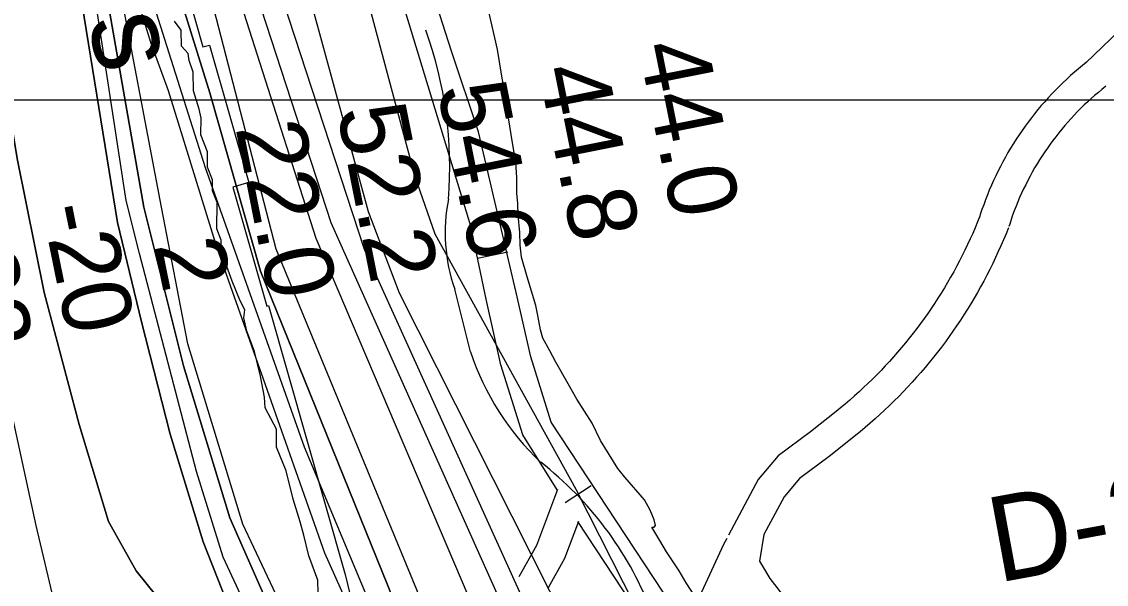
# Model space of a CAD drawing. Extents: x 3250478 to 3288318, y 788638 to 816472.
# Drawn here: x 3277334 to 3278390, y 799603 to 800152 of the extents above; entities that cross this region are included whole.
import ezdxf

# ---------------------------------------------------------------- set-up
doc = ezdxf.new("R2010")
doc.units = 0
for name, color, linetype in [('V-GRID-MAJR', 7, 'Continuous'), ('V-RIVR-EDGE', 7, 'Continuous'), ('V-RIVR-IDEN', 7, 'Continuous'), ('V-RIVR-RANG', 7, 'Continuous'), ('V-RIVR-RANG-IDEN', 7, 'Continuous'), ('V-ROAD-CNTR', 7, 'Continuous'), ('V-RRAP-RVMT', 7, 'Continuous'), ('V-SITE-VEGE', 7, 'Continuous'), ('V-TOPO-DPTH', 7, 'Continuous'), ('V-TOPO-MAJR', 7, 'Continuous'), ('V-TOPO-MINR', 7, 'Continuous'), ('V-TOPO-WATR', 7, 'Continuous')]:
    doc.layers.add(name, color=color, linetype=linetype)

msp = doc.modelspace()

# ---------------------------------------------------------------- linework, layer by layer
at = {"layer": 'V-GRID-MAJR'}
msp.add_spline([(3254640.8, 800084.8), (3259879.3, 800081.4), (3265117.8, 800078.7), (3270356.3, 800076.8), (3275594.8, 800075.6), (3280833.3, 800075.3), (3286071.8, 800075.6)], degree=3, dxfattribs=at)
at = {"layer": 'V-RIVR-EDGE'}
msp.add_lwpolyline([(3277622.9, 799594.3), (3277622.5, 799607.3), (3277613.9, 799631.3), (3277609.1, 799651.3), (3277605.3, 799664.3), (3277598.4, 799686.5), (3277591.9, 799713.9), (3277582.4, 799737), (3277582.4, 799754.4), (3277571.2, 799775.3), (3277570.8, 799785.7), (3277566.9, 799806.1), (3277560.9, 799830.1), (3277553.6, 799850.1), (3277550.5, 799863.1), (3277551.4, 799870.9), (3277547.1, 799879.6), (3277539.3, 799898.8), (3277528.5, 799928.4), (3277528.6, 799938.8), (3277524.2, 799949.7), (3277524.7, 799975.3), (3277520, 799986.6), (3277520, 799997.5), (3277515.3, 800009.7), (3277515.3, 800024.9), (3277508.8, 800041.4), (3277508.9, 800057.5), (3277507.1, 800066.2), (3277501.5, 800084.1), (3277501.2, 800102.3), (3277497.3, 800113.6), (3277496.4, 800120.6), (3277489.9, 800127.6), (3277489.5, 800143.2), (3277483, 800151.9)], dxfattribs=at)
at = {"layer": 'V-ROAD-CNTR'}
for p, q in [((3277778, 799921.2), (3277807.4, 799927.3)), ((3277863.3, 799683.2), (3277888.4, 799699.7))]:
    msp.add_line(p, q, dxfattribs=at)
for points in [[(3279206.2, 801012.6), (3278974.9, 800774.4), (3278783.1, 800571.1), (3278696.4, 800456.4), (3278675.3, 800415.4), (3278649.7, 800380.5), (3278586.3, 800330.4), (3278557.4, 800304.9), (3278515.8, 800254.1), (3278461.1, 800199.6), (3278369.5, 800111.1)], [(3277855.6, 799695.3), (3277822.2, 799748.9), (3277800.7, 799817.2), (3277786.4, 799881.3), (3277771.5, 799952.3), (3277687.1, 800229.7), (3277671.3, 800298.1), (3277660.2, 800373), (3277640.5, 800571.9), (3277629.6, 800720), (3277620.5, 800771.6), (3277617.5, 800779.9), (3277610.4, 800799.8), (3277603, 800812.8), (3277587.2, 800838.8), (3277571.1, 800862.2), (3277549.7, 800897.4)], [(3278293.9, 798738.3), (3278286.8, 798822.7), (3278277.1, 798881.5), (3278266.1, 798928.8), (3278223.6, 799045.9), (3278211.5, 799073.6), (3278202.3, 799097.7), (3278195.5, 799120.9), (3278187.8, 799144.6), (3278182.8, 799165.7), (3278177.1, 799193.2), (3278157.9, 799287), (3278147.5, 799319.4), (3278013, 799513), (3277849.7, 799761.5), (3277829.7, 799825), (3277815.7, 799887.6), (3277778.8, 800044.2), (3277752.5, 800122.8), (3277716.1, 800237.6)], [(3278370.6, 800112), (3278366.7, 800108.9), (3278362.8, 800105.7), (3278358.9, 800102.3), (3278355, 800099), (3278351.3, 800095.5), (3278347.6, 800092), (3278343.9, 800088.5), (3278340.3, 800084.8), (3278336.8, 800081.2), (3278333.3, 800077.4), (3278329.9, 800073.6), (3278326.6, 800069.8), (3278323.3, 800065.9), (3278320.1, 800061.9), (3278316.9, 800057.9), (3278313.8, 800053.8), (3278310.8, 800049.7), (3278307.9, 800045.5), (3278305, 800041.3), (3278302.2, 800037.1), (3278299.4, 800032.8), (3278296.7, 800028.4), (3278294.1, 800024), (3278291.6, 800019.6), (3278289.2, 800015.1), (3278286.8, 800010.6), (3278284.5, 800006.1), (3278282.3, 800001.5), (3278280.1, 799996.8), (3278278, 799992.2), (3278276, 799987.5), (3278274.1, 799982.8), (3278272.3, 799978), (3278270.5, 799973.2), (3278268.8, 799968.4), (3278267.2, 799963.6), (3278266.4, 799960.9)], [(3278389.3, 800088.6), (3278385.6, 800085.6), (3278382.1, 800082.7), (3278378.5, 800079.7), (3278375.1, 800076.6), (3278371.7, 800073.5), (3278368.3, 800070.4), (3278365, 800067.2), (3278361.8, 800063.9), (3278358.6, 800060.6), (3278355.5, 800057.2), (3278352.4, 800053.8), (3278349.4, 800050.3), (3278346.4, 800046.7), (3278343.5, 800043.2), (3278340.6, 800039.5), (3278337.9, 800035.9), (3278335.1, 800032.2), (3278332.5, 800028.4), (3278329.9, 800024.6), (3278327.3, 800020.8), (3278324.9, 800016.9), (3278322.4, 800012.9), (3278320.1, 800009), (3278317.8, 800005), (3278315.6, 800000.9), (3278313.5, 799996.8), (3278311.4, 799992.7), (3278309.4, 799988.6), (3278307.4, 799984.4), (3278305.5, 799980.2), (3278303.7, 799976), (3278302, 799971.7), (3278300.3, 799967.4), (3278298.7, 799963.1), (3278297.2, 799958.7), (3278295.8, 799954.3), (3278295, 799951.9)], [(3278266.8, 799962), (3278264.5, 799956.4), (3278262.2, 799950.8), (3278259.8, 799945.3), (3278257.4, 799939.9), (3278254.9, 799934.5), (3278252.3, 799929.1), (3278249.6, 799923.7), (3278246.9, 799918.4), (3278244.1, 799913.1), (3278241.3, 799907.8), (3278238.3, 799902.6), (3278235.3, 799897.4), (3278232.3, 799892.3), (3278229.2, 799887.2), (3278226, 799882.2), (3278222.7, 799877.1), (3278219.4, 799872.2), (3278216, 799867.2), (3278212.6, 799862.4), (3278209, 799857.5), (3278205.5, 799852.7), (3278201.8, 799848), (3278198.1, 799843.3), (3278194.4, 799838.6), (3278190.5, 799834), (3278186.7, 799829.5), (3278182.7, 799825), (3278178.7, 799820.5), (3278174.7, 799816.1), (3278170.6, 799811.8), (3278166.4, 799807.5), (3278162.2, 799803.3), (3278157.9, 799799.1), (3278153.6, 799795), (3278149.2, 799790.9), (3278144.8, 799786.9), (3278140.3, 799782.9), (3278135.7, 799779), (3278131.1, 799775.2), (3278128.5, 799773)], [(3278294.6, 799950.8), (3278292.3, 799945), (3278289.8, 799939.1), (3278287.3, 799933.3), (3278284.7, 799927.5), (3278282, 799921.7), (3278279.3, 799915.9), (3278276.4, 799910.2), (3278273.5, 799904.6), (3278270.6, 799898.9), (3278267.5, 799893.3), (3278264.4, 799887.8), (3278261.2, 799882.3), (3278258, 799876.8), (3278254.6, 799871.4), (3278251.2, 799866), (3278247.8, 799860.6), (3278244.2, 799855.3), (3278240.6, 799850.1), (3278236.9, 799844.9), (3278233.2, 799839.7), (3278229.4, 799834.6), (3278225.5, 799829.6), (3278221.6, 799824.6), (3278217.6, 799819.6), (3278213.5, 799814.7), (3278209.4, 799809.9), (3278205.2, 799805.1), (3278200.9, 799800.3), (3278196.6, 799795.7), (3278192.2, 799791), (3278187.8, 799786.5), (3278183.3, 799782), (3278178.7, 799777.5), (3278174.1, 799773.1), (3278169.5, 799768.8), (3278164.8, 799764.5), (3278160, 799760.3), (3278155.1, 799756.1), (3278150.3, 799752.1), (3278147.5, 799749.8)], [(3277771.1, 799830), (3277755.8, 799891)], [(3278128.6, 799773.1), (3278102, 799751.8), (3278070.6, 799728.5), (3278051.2, 799705.5), (3278022.3, 799651.3)], [(3278147.3, 799749.7), (3278120.3, 799728), (3278091.3, 799706.5), (3278076.2, 799688.6), (3278056.6, 799651.9)], [(3277855.9, 799695.8), (3277835.3, 799641.1), (3277818.3, 799610.7)], [(3277876.2, 799664.6), (3277862.5, 799628.5), (3277846.6, 799600)], [(3278271.3, 798417), (3278259.6, 798458.4), (3278253, 798493.7), (3278253, 798516.9), (3278254.7, 798547.2), (3278260.8, 798616.3), (3278264.9, 798670.5), (3278263.9, 798736.8), (3278257, 798818.9), (3278247.6, 798875.7), (3278237, 798921.3), (3278226.4, 798958.6), (3278158.9, 799136.5), (3278153.5, 799159.2), (3278147.7, 799187.2), (3278128.9, 799279.3), (3277937, 799571.3), (3277875.6, 799664.6)], [(3278056.6, 799651.9), (3278052.5, 799626), (3278055.3, 799621.2)], [(3278020.6, 799648.2), (3278017.4, 799642.2), (3277976.4, 799553.6)], [(3278055.3, 799621.2), (3278062.3, 799609.1), (3278108.5, 799549.8), (3278132.3, 799509.1), (3278142.7, 799477.8)]]:
    msp.add_lwpolyline(points, dxfattribs=at)
for centre, radius, start, end in [((3277353.6, 800009.4), 397.3, 355.5654, 19.6998), ((3277913.3, 799946.1), 166.9, 168.7185, 199.2768), ((3278019.3, 799912), 261.4, 198.2915, 226.5653), ((3277630.5, 799454.8), 339.5, 21.6518, 51.9798)]:
    msp.add_arc(centre, radius, start, end, dxfattribs=at)
at = {"layer": 'V-RRAP-RVMT'}
for p, q in [((3277477.9, 800242.4), (3277510.7, 800126.9)), ((3277510.7, 800126.9), (3277517.3, 800128.8)), ((3277517.3, 800128.8), (3277555.4, 799994.8)), ((3277555.4, 799994.8), (3277539.9, 799990.3)), ((3277539.9, 799990.3), (3277573, 799874.4)), ((3277573, 799874.4), (3277574.7, 799874.9)), ((3277574.7, 799874.9), (3277649.1, 799612.9)), ((3277649.1, 799612.9), (3277681.5, 799481.6))]:
    msp.add_line(p, q, dxfattribs=at)
at = {"layer": 'V-SITE-VEGE'}
for p, q in [((3277797.5, 800124.5), (3277788.8, 800162.6)), ((3277801.4, 800100.3), (3277797.5, 800124.5)), ((3277804, 800085.8), (3277801.4, 800100.3)), ((3277806.8, 800065.9), (3277804, 800085.8)), ((3277810.8, 800041.7), (3277806.8, 800065.9)), ((3277813.5, 800023.9), (3277810.8, 800041.7)), ((3277815.4, 800014.3), (3277813.5, 800023.9)), ((3277816.3, 799999.7), (3277815.4, 800014.3)), ((3277816.3, 799984.6), (3277816.3, 799999.7)), ((3277817.1, 799974.3), (3277816.3, 799984.6)), ((3277817.4, 799963), (3277817.1, 799974.3)), ((3277819, 799946.3), (3277817.4, 799963)), ((3277819.4, 799933.9), (3277819, 799946.3)), ((3277820.8, 799922.1), (3277819.4, 799933.9)), ((3277826.3, 799902.8), (3277820.8, 799922.1)), ((3277834.7, 799874.9), (3277826.3, 799902.8)), ((3277836.6, 799865.3), (3277834.7, 799874.9)), ((3277839.2, 799851.3), (3277836.6, 799865.3)), ((3277841.6, 799843.3), (3277839.2, 799851.3)), ((3277848.4, 799831), (3277841.6, 799843.3)), ((3277854.1, 799819.9), (3277848.4, 799831)), ((3277866.1, 799798.6), (3277854.1, 799819.9)), ((3277874.7, 799783.7), (3277866.1, 799798.6)), ((3277889.4, 799760.4), (3277874.7, 799783.7)), ((3277897.5, 799743.4), (3277889.4, 799760.4)), ((3277914.5, 799716.3), (3277897.5, 799743.4)), ((3277921.2, 799707.9), (3277914.5, 799716.3)), ((3277940.3, 799685.8), (3277921.2, 799707.9)), ((3277946, 799675.7), (3277940.3, 799685.8)), ((3277950, 799666.1), (3277946, 799675.7)), ((3277949.7, 799659), (3277951.3, 799660.7)), ((3277951.3, 799660.7), (3277950, 799666.1)), ((3277955.5, 799646.2), (3277947.6, 799659)), ((3277947.6, 799659), (3277949.7, 799659)), ((3277961.8, 799635.1), (3277955.5, 799646.2)), ((3277974.2, 799616.5), (3277961.8, 799635.1)), ((3277981.1, 799604.9), (3277974.2, 799616.5)), ((3277990.7, 799590), (3277981.1, 799604.9))]:
    msp.add_line(p, q, dxfattribs=at)
at = {"layer": 'V-TOPO-DPTH'}
for points in [[(3278043.5, 798542.7), (3277830.5, 799256.4), (3277566.9, 799908.5), (3277517.6, 800082.3), (3277468.3, 800241), (3277429.8, 800571.3), (3277421.2, 800642.1), (3277410.6, 800987.4), (3277400, 801210.5), (3277393.5, 801266.3), (3277350.7, 801538.7), (3277329.3, 801695.2), (3277325.1, 801815.3), (3277325.1, 801924.7), (3277278.1, 802561.8), (3277267.4, 802639), (3277188.2, 803185.9), (3277171.1, 803391.8), (3277162.6, 803604.2), (3277160.5, 803885.2), (3277160.6, 804026.7), (3277152, 804061), (3277098.4, 804232.6), (3276937.7, 804777.5)], [(3276847.8, 804710), (3276986.9, 804194.1), (3277031.9, 804016), (3277102.5, 803454.1), (3277138.9, 803192.4), (3277158.1, 803005.8), (3277207.3, 802486.7), (3277260.7, 801884), (3277305.7, 801504.4), (3277359.2, 801223.4), (3277382.6, 800685), (3277391.2, 800526.3), (3277412.5, 800204.6), (3277453.2, 799970.8), (3277491.8, 799816.3), (3277536.8, 799668.3), (3277575.4, 799580.4), (3277620.4, 799498.8), (3277676.1, 799421.6), (3277755.4, 799312.2), (3277770.4, 799280), (3277813.3, 799119.2), (3277974, 798523.5)], [(3277974, 798523.5), (3277813.3, 799119.2), (3277770.4, 799280), (3277755.4, 799312.2), (3277676.1, 799421.6), (3277620.4, 799498.8), (3277575.4, 799580.4), (3277536.8, 799668.3), (3277491.8, 799816.3), (3277453.2, 799970.8), (3277412.5, 800204.6), (3277391.2, 800526.3), (3277382.6, 800685), (3277359.2, 801223.4), (3277305.7, 801504.4), (3277260.7, 801884), (3277207.3, 802486.7), (3277158.1, 803005.8), (3277138.9, 803192.4), (3277102.5, 803454.1), (3277031.9, 804016), (3276986.9, 804194.1), (3276847.8, 804710)], [(3277384.9, 801221.2), (3277410.5, 800597.1), (3277434, 800236.7), (3277434, 800215.3), (3277459.7, 800131.6), (3277476.8, 800084.4), (3277524, 799932.1), (3277573.3, 799792.7), (3277629, 799634), (3277676.1, 799528.9), (3277721.2, 799421.6), (3277770.5, 799320.8), (3277791.9, 799282.2), (3277839, 799091.3), (3278011, 798533.7)], [(3277384.9, 801221.2), (3277410.5, 800597.1), (3277434, 800236.7), (3277434, 800215.3), (3277459.7, 800131.6), (3277476.8, 800084.4), (3277524, 799932.1), (3277573.3, 799792.7), (3277629, 799634), (3277676.1, 799528.9), (3277721.2, 799421.6), (3277770.5, 799320.8), (3277791.9, 799282.2), (3277839, 799091.3), (3278011, 798533.7)], [(3276789.3, 799207.8), (3276858.5, 799246.1), (3276865.5, 799249.3), (3277370.8, 799382.9), (3277382.2, 799397.5), (3277388.4, 799421.9), (3277391.8, 799446.3), (3277391, 799471), (3277387.4, 799495.9), (3277348.6, 799660.8), (3277325, 799768.5), (3277303.6, 799876.6), (3277285.4, 799985.3), (3277269.4, 800094.4), (3277225.6, 800429.4), (3277223.2, 800450.5), (3277221.2, 800471.7), (3277219.9, 800492.8), (3277219.1, 800514.1), (3277218.7, 800535.3), (3277218.4, 800556.6), (3277218.1, 800577.8), (3277217.9, 800599.1), (3277214.3, 801050.6)], [(3276789.3, 799207.8), (3276858.5, 799246.1), (3276865.5, 799249.3), (3277370.8, 799382.9), (3277382.2, 799397.5), (3277388.4, 799421.9), (3277391.8, 799446.3), (3277391, 799471), (3277387.4, 799495.9), (3277348.6, 799660.8), (3277325, 799768.5), (3277303.6, 799876.6), (3277285.4, 799985.3), (3277269.4, 800094.4), (3277225.6, 800429.4), (3277223.2, 800450.5), (3277221.2, 800471.7), (3277219.9, 800492.8), (3277219.1, 800514.1), (3277218.7, 800535.3), (3277218.4, 800556.6), (3277218.1, 800577.8), (3277217.9, 800599.1), (3277214.3, 801050.6)], [(3277418.9, 799664.6), (3277390.2, 799759), (3277356.3, 799887.7), (3277329.9, 800018.1), (3277308.4, 800149.6), (3277282.9, 800339.7), (3277278.4, 800377.1), (3277274.8, 800414.6), (3277272.3, 800452.2), (3277270.5, 800489.9), (3277269.4, 800527.6), (3277268.5, 800565.3), (3277267.7, 800603), (3277267, 800640.7), (3277261.7, 800970.1)], [(3277261.7, 800970.1), (3277267, 800640.7), (3277267.7, 800603), (3277268.5, 800565.3), (3277269.4, 800527.6), (3277270.5, 800489.9), (3277272.3, 800452.2), (3277274.8, 800414.6), (3277278.4, 800377.1), (3277282.9, 800339.7), (3277308.4, 800149.6), (3277329.9, 800018.1), (3277356.3, 799887.7), (3277390.2, 799759), (3277418.9, 799664.6)], [(3277917.5, 798507.9), (3277847.5, 798838.2), (3277800.4, 799041.9), (3277772.6, 799194.2), (3277761.9, 799245.7), (3277740.4, 799297.2), (3277706.1, 799340.1), (3277678.2, 799368), (3277637.5, 799413.1), (3277573.2, 799505.3), (3277538.9, 799573.9), (3277511, 799644.7), (3277478.9, 799749.8), (3277451, 799859.2), (3277427.5, 799955.8), (3277393.2, 800168.1), (3277371.8, 800399.7), (3277359, 800586.4), (3277354.8, 800674.3), (3277342, 800959.6)], [(3277342, 800959.6), (3277354.8, 800674.3), (3277359, 800586.4), (3277371.8, 800399.7), (3277393.2, 800168.1), (3277427.5, 799955.8), (3277451, 799859.2), (3277478.9, 799749.8), (3277511, 799644.7), (3277538.9, 799573.9), (3277573.2, 799505.3), (3277637.5, 799413.1), (3277678.2, 799368), (3277706.1, 799340.1), (3277740.4, 799297.2), (3277761.9, 799245.7), (3277772.6, 799194.2), (3277800.4, 799041.9), (3277847.5, 798838.2), (3277917.5, 798507.9)], [(3277550.7, 798620.5), (3277651.3, 798730.5), (3277705.2, 798818.6), (3277727.2, 798904.2), (3277754.2, 799036.4), (3277759.1, 799114.7), (3277761.6, 799175.9), (3277754.2, 799232.2), (3277710.2, 799313), (3277683.3, 799337.5), (3277605, 799410.9), (3277565.8, 799472.2), (3277504.7, 799543.2), (3277445.9, 799616.6), (3277418.9, 799664.6)], [(3277418.9, 799664.6), (3277445.9, 799616.6), (3277504.7, 799543.2), (3277565.8, 799472.2), (3277605, 799410.9), (3277683.3, 799337.5), (3277710.2, 799313), (3277754.2, 799232.2), (3277761.6, 799175.9), (3277759.1, 799114.7), (3277754.2, 799036.4), (3277727.2, 798904.2), (3277705.2, 798818.6), (3277651.3, 798730.5), (3277550.7, 798620.5)]]:
    msp.add_lwpolyline(points, dxfattribs=at)
at = {"layer": 'V-TOPO-MAJR'}
msp.add_lwpolyline([(3278089.2, 798555.3), (3277935.6, 799284.3), (3277764.1, 799668.2), (3277635.5, 799955.7), (3277543.4, 800238.8), (3277487.7, 800500.5), (3277466.3, 800777.2), (3277455.7, 801043.2), (3277457.9, 801261.9), (3277460.9, 801413.8)], dxfattribs=at)
at = {"layer": 'V-TOPO-MINR'}
for points in [[(3277012.1, 804812.6), (3277098.5, 804462.1), (3277184.1, 804046), (3277201.2, 803831.5), (3277207.5, 803284.6), (3277220.4, 803181.6), (3277250.3, 803016.5), (3277308.1, 802593.9), (3277380.8, 801791.7), (3277395.7, 801493.6), (3277434.3, 801227.6), (3277440.6, 800976.7), (3277457.7, 800663.5), (3277476.9, 800455.5), (3277521.9, 800249.6), (3277620.5, 799940.7), (3277903.4, 799275.7), (3277929.1, 799177), (3277978.4, 798930.4), (3278074.4, 798551.2)], [(3278059.9, 798547.2), (3277851.9, 799275.7), (3277581.9, 799930), (3277496.2, 800262.4), (3277461.9, 800457.6), (3277447.5, 800598.2), (3277408.5, 801244.8), (3277389.3, 801375.6), (3277350.8, 801675.9), (3277342.2, 801869), (3277291, 802566), (3277250.3, 802883.5), (3277196.8, 803218.1), (3277181.8, 803456.2), (3277177.7, 803857.3), (3277173.4, 804028.9), (3277149.9, 804118.9), (3276984.3, 804796.1)], [(3278027.2, 798538.2), (3277935.5, 798806), (3277806.9, 799254.3), (3277796.2, 799290.8), (3277609.7, 799736.9), (3277513.3, 800009.3), (3277446.8, 800219.6), (3277436.2, 800393.3), (3277416.9, 800624.9), (3277391.4, 801225.5), (3277350.7, 801463.6), (3277288.6, 801905.4), (3277256.6, 802379.5), (3277241.6, 802615.4), (3277166.7, 803211.7), (3277145.4, 803477.6), (3277126.2, 803812.2), (3277113.4, 804043.9), (3277098.4, 804116.8), (3277002, 804462.2), (3276914.1, 804773.2)], [(3276937.7, 804777.5), (3277098.4, 804232.6), (3277152, 804061), (3277160.6, 804026.7), (3277160.5, 803885.2), (3277162.6, 803604.2), (3277171.1, 803391.8), (3277188.2, 803185.9), (3277267.4, 802639), (3277278.1, 802561.8), (3277325.1, 801924.7), (3277325.1, 801815.3), (3277329.3, 801695.2), (3277350.7, 801538.7), (3277393.5, 801266.3), (3277400, 801210.5), (3277410.6, 800987.4), (3277421.2, 800642.1), (3277429.8, 800571.3), (3277468.3, 800241), (3277517.6, 800082.3), (3277566.9, 799908.5), (3277830.5, 799256.4), (3278043.5, 798542.7)], [(3276847.8, 804710), (3276986.9, 804194.1), (3277031.9, 804016), (3277102.5, 803454.1), (3277138.9, 803192.4), (3277158.1, 803005.8), (3277207.3, 802486.7), (3277260.7, 801884), (3277305.7, 801504.4), (3277359.2, 801223.4), (3277382.6, 800685), (3277391.2, 800526.3), (3277412.5, 800204.6), (3277453.2, 799970.8), (3277491.8, 799816.3), (3277536.8, 799668.3), (3277575.4, 799580.4), (3277620.4, 799498.8), (3277676.1, 799421.6), (3277755.4, 799312.2), (3277770.4, 799280), (3277813.3, 799119.2), (3277974, 798523.5)], [(3278153.5, 798573), (3277999.9, 799290.7), (3277939.9, 799415.1), (3277702, 799887), (3277672, 799966.4), (3277605.6, 800208.8), (3277534.9, 800607.7), (3277519.9, 800809.4), (3277511.4, 801096.8), (3277509.4, 801300.5), (3277502.5, 801423.4)], [(3277523.3, 801428.2), (3277537.2, 801268.4), (3277556.4, 800938), (3277584.2, 800657.1), (3277618.5, 800369.6), (3277717, 800000.7), (3277736.3, 799944.9), (3277873.5, 799696.1), (3278023.6, 799400.1), (3278072.9, 799329.3), (3278109.3, 799217.7), (3278130.7, 799071.9), (3278143.5, 798831.7), (3278179.5, 798580.2)], [(3277481.7, 801418.6), (3277481.5, 801379.9), (3277477.2, 801223.3), (3277477.1, 800884.4), (3277500.6, 800567), (3277543.4, 800350.4), (3277588.4, 800172.3), (3277667.7, 799929.9), (3277954.9, 799295), (3277965.6, 799262.8), (3278010.6, 799041.9), (3278115, 798562.4)], [(3277950.1, 798516.9), (3277800.4, 799117), (3277781.1, 799207.1), (3277759.7, 799277.9), (3277740.4, 799316.5), (3277654.7, 799413), (3277586.1, 799509.6), (3277530.3, 799629.7), (3277504.6, 799713.4), (3277448.9, 799925.7), (3277436.1, 799977.2), (3277403.9, 800187.4), (3277395.4, 800294.6), (3277376.2, 800539.2), (3277359.1, 800848), (3277339.9, 801247)], [(3277993, 798528.7), (3277796.2, 799220), (3277776.9, 799288.6), (3277753.3, 799335.8), (3277689, 799423.8), (3277603.2, 799548.2), (3277549.6, 799661.9), (3277496.1, 799837.8), (3277470.4, 799970.8), (3277425.4, 800208.8), (3277414.7, 800376.1), (3277397.6, 800650.7), (3277376.4, 801219.1)], [(3276789.3, 799207.8), (3276858.5, 799246.1), (3276865.5, 799249.3), (3277370.8, 799382.9), (3277382.2, 799397.5), (3277388.4, 799421.9), (3277391.8, 799446.3), (3277391, 799471), (3277387.4, 799495.9), (3277348.6, 799660.8), (3277325, 799768.5), (3277303.6, 799876.6), (3277285.4, 799985.3), (3277269.4, 800094.4), (3277225.6, 800429.4), (3277223.2, 800450.5), (3277221.2, 800471.7), (3277219.9, 800492.8), (3277219.1, 800514.1), (3277218.7, 800535.3), (3277218.4, 800556.6), (3277218.1, 800577.8), (3277217.9, 800599.1), (3277214.3, 801050.6)], [(3277418.9, 799664.6), (3277390.2, 799759), (3277356.3, 799887.7), (3277329.9, 800018.1), (3277308.4, 800149.6), (3277282.9, 800339.7), (3277278.4, 800377.1), (3277274.8, 800414.6), (3277272.3, 800452.2), (3277270.5, 800489.9), (3277269.4, 800527.6), (3277268.5, 800565.3), (3277267.7, 800603), (3277267, 800640.7), (3277261.7, 800970.1)], [(3277342, 800959.6), (3277354.8, 800674.3), (3277359, 800586.4), (3277371.8, 800399.7), (3277393.2, 800168.1), (3277427.5, 799955.8), (3277451, 799859.2), (3277478.9, 799749.8), (3277511, 799644.7), (3277538.9, 799573.9), (3277573.2, 799505.3), (3277637.5, 799413.1), (3277678.2, 799368), (3277706.1, 799340.1), (3277740.4, 799297.2), (3277761.9, 799245.7), (3277772.6, 799194.2), (3277800.4, 799041.9), (3277847.5, 798838.2), (3277917.5, 798507.9)], [(3277550.7, 798620.5), (3277651.3, 798730.5), (3277705.2, 798818.6), (3277727.2, 798904.2), (3277754.2, 799036.4), (3277759.1, 799114.7), (3277761.6, 799175.9), (3277754.2, 799232.2), (3277710.2, 799313), (3277683.3, 799337.5), (3277605, 799410.9), (3277565.8, 799472.2), (3277504.7, 799543.2), (3277445.9, 799616.6), (3277418.9, 799664.6)]]:
    msp.add_lwpolyline(points, dxfattribs=at)
at = {"layer": 'V-TOPO-WATR'}
msp.add_lwpolyline([(3277384.9, 801221.2), (3277410.5, 800597.1), (3277434, 800236.7), (3277434, 800215.3), (3277459.7, 800131.6), (3277476.8, 800084.4), (3277524, 799932.1), (3277573.3, 799792.7), (3277629, 799634), (3277676.1, 799528.9), (3277721.2, 799421.6), (3277770.5, 799320.8), (3277791.9, 799282.2), (3277839, 799091.3), (3278011, 798533.7)], dxfattribs=at)

# ---------------------------------------------------------------- texts
at = {"layer": 'V-RIVR-IDEN'}
msp.add_text(' Photos', height=83, rotation=282.7081, dxfattribs=at).set_placement((3277328, 800465.6))
at = {"layer": 'V-RIVR-RANG'}
for s, rotation, p in [('44.0', 281.2683, (3277934.4, 800127.5)), ('44.8', 281.2683, (3277837, 800104.8)), ('54.6', 281.2683, (3277738.6, 800086.9)), ('52.2', 281.2683, (3277640.9, 800065.3)), ('22.0', 281.2683, (3277542.3, 800048.4)), ('-20', 281.4913, (3277353.7, 799970.1)), ('-33', 281.4913, (3277255.1, 799953.1)), ('2', 281.4913, (3277463, 799934.3))]:
    msp.add_text(s, height=67, rotation=rotation, dxfattribs=at).set_placement(p)
at = {"layer": 'V-RIVR-RANG-IDEN'}
msp.add_text('D-200', height=83, rotation=10.4373, dxfattribs=at).set_placement((3278284.1, 799604.8))

doc.saveas('drawing.dxf')
